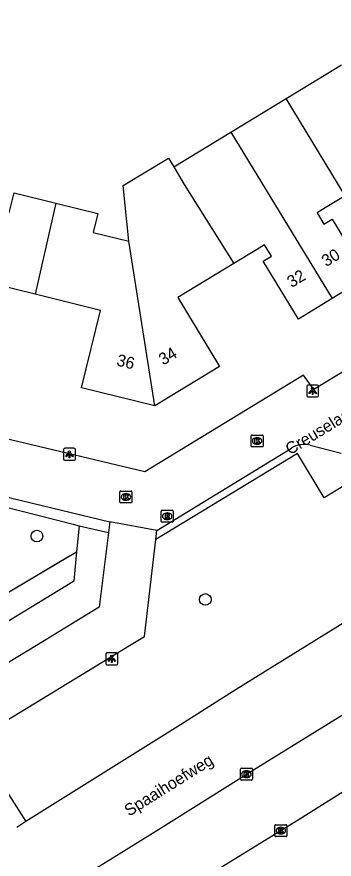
# Model space of a CAD drawing. Extents: x 157767 to 159171, y 387842 to 389425.
# Drawn here: x 158221.8 to 158248.5, y 388232 to 388302.9 of the extents above; entities that cross this region are included whole.
import ezdxf

# ---------------------------------------------------------------- set-up
doc = ezdxf.new("R2010")
doc.units = 0
for name, color, linetype in [('IMGEO_Boom', 7, 'Continuous'), ('IMGEO_Fietspad_gesloten', 7, 'Continuous'), ('IMGEO_Groenvoorziening', 7, 'Continuous'), ('IMGEO_Kolk', 7, 'Continuous'), ('IMGEO_Lichtpunt', 7, 'Continuous'), ('IMGEO_Muur', 7, 'Continuous'), ('IMGEO_Openbare_ruimte_label', 7, 'Continuous'), ('IMGEO_Pand', 7, 'Continuous'), ('IMGEO_Pand_nummerreeks', 7, 'Continuous'), ('IMGEO_Rijbaan_lokaal_gesloten', 7, 'Continuous'), ('IMGEO_Rijbaan_lokaal_open', 7, 'Continuous'), ('IMGEO_Rioolput', 7, 'Continuous'), ('IMGEO_Voetpad_open', 7, 'Continuous')]:
    doc.layers.add(name, color=color, linetype=linetype)

msp = doc.modelspace()

# ---------------------------------------------------------------- linework, layer by layer
at = {"layer": 'IMGEO_Boom'}
for centre in [(158223.515, 388259.204), (158237.678, 388253.874)]:
    msp.add_circle(centre, 0.489, dxfattribs=at)
at = {"layer": 'IMGEO_Fietspad_gesloten'}
for points in [[(158229.644, 388260.394), (158229.533, 388259.494)], [(158233.501, 388258.911), (158233.592, 388259.688)], [(158229.533, 388259.494), (158228.757, 388253.218), (158223.468, 388250), (158218.876, 388247.24), (158215.245, 388245.012)], [(158218.642, 388242.296), (158231.308, 388250), (158232.551, 388250.756), (158233.501, 388258.911)]]:
    msp.add_lwpolyline(points, dxfattribs=at)
at = {"layer": 'IMGEO_Groenvoorziening'}
msp.add_lwpolyline([(158198.647, 388271.084), (158207.528, 388256.281), (158219.17, 388253.347), (158226.854, 388257.889)], dxfattribs=at)
at = {"layer": 'IMGEO_Kolk'}
for p, q in [((158241.53, 388266.778), (158241.53, 388267.63)), ((158241.605, 388267.704), (158242.457, 388267.704)), ((158242.018, 388267.484), (158242.043, 388267.484)), ((158242.531, 388267.63), (158242.531, 388266.778)), ((158242.457, 388266.704), (158241.605, 388266.704)), ((158242.041, 388266.924), (158242.016, 388266.924)), ((158230.501, 388262.067), (158230.501, 388262.919)), ((158230.576, 388262.993), (158231.428, 388262.993)), ((158230.989, 388262.773), (158231.014, 388262.773)), ((158231.502, 388262.919), (158231.502, 388262.067)), ((158231.428, 388261.993), (158230.576, 388261.993)), ((158231.012, 388262.213), (158230.987, 388262.213)), ((158240.63, 388238.755), (158240.63, 388239.607)), ((158240.705, 388239.681), (158241.557, 388239.681)), ((158241.118, 388239.461), (158241.143, 388239.461)), ((158241.631, 388239.607), (158241.631, 388238.755)), ((158241.557, 388238.681), (158240.705, 388238.681)), ((158241.141, 388238.901), (158241.116, 388238.901)), ((158243.525, 388234.007), (158243.525, 388234.859)), ((158243.6, 388234.933), (158244.452, 388234.933)), ((158244.526, 388234.859), (158244.526, 388234.007)), ((158244.036, 388234.153), (158244.011, 388234.153)), ((158244.013, 388234.713), (158244.038, 388234.713)), ((158244.452, 388233.933), (158243.6, 388233.933))]:
    msp.add_line(p, q, dxfattribs=at)
for points in [[(158241.53, 388266.778), (158241.53, 388267.63)], [(158241.605, 388267.704), (158242.457, 388267.704)], [(158241.851, 388267.404), (158241.974, 388267.404), (158241.974, 388267.253), (158242.104, 388267.404), (158242.268, 388267.404), (158242.122, 388267.253), (158242.275, 388267.004), (158242.123, 388267.004), (158242.038, 388267.168), (158241.974, 388267.101), (158241.974, 388267.004), (158241.851, 388267.004), (158241.851, 388267.404)], [(158242.531, 388267.63), (158242.531, 388266.778)], [(158242.457, 388266.704), (158241.605, 388266.704)], [(158230.501, 388262.067), (158230.501, 388262.919)], [(158230.576, 388262.993), (158231.428, 388262.993)], [(158230.822, 388262.693), (158230.945, 388262.693), (158230.945, 388262.542), (158231.075, 388262.693), (158231.239, 388262.693), (158231.093, 388262.542), (158231.246, 388262.293), (158231.094, 388262.293), (158231.009, 388262.457), (158230.945, 388262.39), (158230.945, 388262.293), (158230.822, 388262.293), (158230.822, 388262.693)], [(158231.502, 388262.919), (158231.502, 388262.067)], [(158231.428, 388261.993), (158230.576, 388261.993)], [(158240.63, 388238.755), (158240.63, 388239.607)], [(158240.705, 388239.681), (158241.557, 388239.681)], [(158240.951, 388239.381), (158241.074, 388239.381), (158241.074, 388239.23), (158241.204, 388239.381), (158241.368, 388239.381), (158241.222, 388239.23), (158241.375, 388238.981), (158241.223, 388238.981), (158241.138, 388239.145), (158241.074, 388239.078), (158241.074, 388238.981), (158240.951, 388238.981), (158240.951, 388239.381)], [(158241.631, 388239.607), (158241.631, 388238.755)], [(158241.557, 388238.681), (158240.705, 388238.681)], [(158243.525, 388234.007), (158243.525, 388234.859)], [(158243.6, 388234.933), (158244.452, 388234.933)], [(158244.526, 388234.859), (158244.526, 388234.007)], [(158243.846, 388234.633), (158243.969, 388234.633), (158243.969, 388234.482), (158244.099, 388234.633), (158244.263, 388234.633), (158244.117, 388234.482), (158244.27, 388234.233), (158244.118, 388234.233), (158244.033, 388234.397), (158243.969, 388234.33), (158243.969, 388234.233), (158243.846, 388234.233), (158243.846, 388234.633)], [(158244.452, 388233.933), (158243.6, 388233.933)]]:
    msp.add_lwpolyline(points, dxfattribs=at)
for centre, start, end in [((158241.607, 388267.628), 91.55205, 178.44795), ((158241.607, 388267.628), 91.55205, 178.44795), ((158242.455, 388267.628), 1.55205, 88.44795), ((158242.455, 388267.628), 1.55205, 88.44795), ((158241.607, 388266.78), 181.55205, 268.44795), ((158241.607, 388266.78), 181.55205, 268.44795), ((158242.455, 388266.78), 271.55205, 358.44795), ((158242.455, 388266.78), 271.55205, 358.44795), ((158230.578, 388262.917), 91.55205, 178.44795), ((158230.578, 388262.917), 91.55205, 178.44795), ((158231.426, 388262.917), 1.55205, 88.44795), ((158231.426, 388262.917), 1.55205, 88.44795), ((158230.578, 388262.069), 181.55205, 268.44795), ((158230.578, 388262.069), 181.55205, 268.44795), ((158231.426, 388262.069), 271.55205, 358.44795), ((158231.426, 388262.069), 271.55205, 358.44795), ((158240.707, 388239.605), 91.55205, 178.44795), ((158240.707, 388239.605), 91.55205, 178.44795), ((158241.555, 388239.605), 1.55205, 88.44795), ((158241.555, 388239.605), 1.55205, 88.44795), ((158240.707, 388238.757), 181.55205, 268.44795), ((158240.707, 388238.757), 181.55205, 268.44795), ((158241.555, 388238.757), 271.55205, 358.44795), ((158241.555, 388238.757), 271.55205, 358.44795), ((158243.602, 388234.857), 91.55205, 178.44795), ((158243.602, 388234.857), 91.55205, 178.44795), ((158244.45, 388234.857), 1.55205, 88.44795), ((158244.45, 388234.857), 1.55205, 88.44795), ((158243.602, 388234.009), 181.55205, 268.44795), ((158243.602, 388234.009), 181.55205, 268.44795), ((158244.45, 388234.009), 271.55205, 358.44795), ((158244.45, 388234.009), 271.55205, 358.44795)]:
    msp.add_arc(centre, 0.0765, start, end, dxfattribs=at)
for centre, major_axis, ratio, start_param, end_param in [((158242.017, 388267.204), (-0.387, 0.002), 0.722429, 4.712389, 7.853982), ((158242.042, 388267.204), (-0.39, 0.002), 0.717154, 1.570796, 4.712389), ((158230.988, 388262.493), (-0.387, 0.002), 0.722429, 4.712389, 7.853982), ((158231.013, 388262.493), (-0.39, 0.002), 0.717154, 1.570796, 4.712389), ((158241.117, 388239.181), (-0.387, 0.002), 0.722429, 4.712389, 7.853982), ((158241.142, 388239.181), (-0.39, 0.002), 0.717154, 1.570796, 4.712389), ((158244.012, 388234.433), (-0.387, 0.002), 0.722429, 4.712389, 7.853982), ((158244.037, 388234.433), (-0.39, 0.002), 0.717154, 1.570796, 4.712389)]:
    msp.add_ellipse(centre, major_axis=major_axis, ratio=ratio, start_param=start_param, end_param=end_param, dxfattribs=at)
at = {"layer": 'IMGEO_Lichtpunt'}
for p, q in [((158246.203, 388271.808), (158246.203, 388271.001)), ((158246.203, 388271.808), (158246.203, 388271.001)), ((158247.105, 388271.903), (158246.297, 388271.903)), ((158247.105, 388271.903), (158246.297, 388271.903)), ((158247.199, 388271.001), (158247.199, 388271.808)), ((158247.199, 388271.001), (158247.199, 388271.808)), ((158246.297, 388270.907), (158247.105, 388270.907)), ((158246.297, 388270.907), (158247.105, 388270.907)), ((158225.752, 388266.489), (158225.752, 388265.682)), ((158225.752, 388266.489), (158225.752, 388265.682)), ((158226.654, 388266.584), (158225.846, 388266.584)), ((158226.654, 388266.584), (158225.846, 388266.584)), ((158226.748, 388265.682), (158226.748, 388266.489)), ((158226.748, 388265.682), (158226.748, 388266.489)), ((158225.846, 388265.588), (158226.654, 388265.588)), ((158225.846, 388265.588), (158226.654, 388265.588)), ((158229.313, 388249.288), (158229.313, 388248.481)), ((158229.313, 388249.288), (158229.313, 388248.481)), ((158230.215, 388249.383), (158229.407, 388249.383)), ((158230.215, 388249.383), (158229.407, 388249.383)), ((158230.309, 388248.481), (158230.309, 388249.288)), ((158230.309, 388248.481), (158230.309, 388249.288)), ((158229.407, 388248.387), (158230.215, 388248.387)), ((158229.407, 388248.387), (158230.215, 388248.387))]:
    msp.add_line(p, q, dxfattribs=at)
for points in [[(158246.577, 388271.472), (158246.616, 388271.444), (158246.428, 388271.182), (158246.39, 388271.209), (158246.577, 388271.472)], [(158246.679, 388271.424), (158246.726, 388271.424), (158246.726, 388271.102), (158246.679, 388271.102), (158246.679, 388271.424)], [(158246.789, 388271.444), (158246.827, 388271.471), (158247.014, 388271.209), (158246.975, 388271.181), (158246.789, 388271.444)], [(158226.126, 388266.153), (158226.165, 388266.125), (158225.977, 388265.863), (158225.939, 388265.89), (158226.126, 388266.153)], [(158226.228, 388266.105), (158226.275, 388266.105), (158226.275, 388265.783), (158226.228, 388265.783), (158226.228, 388266.105)], [(158226.338, 388266.125), (158226.376, 388266.152), (158226.563, 388265.89), (158226.524, 388265.862), (158226.338, 388266.125)], [(158229.687, 388248.952), (158229.726, 388248.924), (158229.538, 388248.662), (158229.5, 388248.689), (158229.687, 388248.952)], [(158229.899, 388248.924), (158229.937, 388248.951), (158230.124, 388248.689), (158230.085, 388248.661), (158229.899, 388248.924)], [(158229.789, 388248.904), (158229.836, 388248.904), (158229.836, 388248.582), (158229.789, 388248.582), (158229.789, 388248.904)]]:
    msp.add_lwpolyline(points, dxfattribs=at)
for centre in [(158246.702, 388271.606), (158226.251, 388266.287), (158229.812, 388249.086)]:
    msp.add_circle(centre, 0.0994, dxfattribs=at)
for centre, start, end in [((158246.297, 388271.808), 90, 180), ((158246.297, 388271.808), 90, 180), ((158247.105, 388271.808), 0, 90), ((158247.105, 388271.808), 0, 90), ((158246.297, 388271.001), 180, 270), ((158246.297, 388271.001), 180, 270), ((158247.105, 388271.001), 270, 0), ((158247.105, 388271.001), 270, 360), ((158225.846, 388266.489), 90, 180), ((158225.846, 388266.489), 90, 180), ((158226.654, 388266.489), 0, 90), ((158226.654, 388266.489), 0, 90), ((158225.846, 388265.682), 180, 270), ((158225.846, 388265.682), 180, 270), ((158226.654, 388265.682), 270, 0), ((158226.654, 388265.682), 270, 360), ((158229.407, 388249.288), 90, 180), ((158229.407, 388249.288), 90, 180), ((158230.215, 388249.288), 0, 90), ((158230.215, 388249.288), 0, 90), ((158229.407, 388248.481), 180, 270), ((158229.407, 388248.481), 180, 270), ((158230.215, 388248.481), 270, 0), ((158230.215, 388248.481), 270, 360)]:
    msp.add_arc(centre, 0.0946, start, end, dxfattribs=at)
at = {"layer": 'IMGEO_Muur'}
msp.add_lwpolyline([(158198.647, 388271.084), (158207.528, 388256.281), (158219.17, 388253.347), (158226.246, 388257.53)], dxfattribs=at)
at = {"layer": 'IMGEO_Pand'}
for points in [[(158244.472, 388296.002), (158249.114, 388298.821)], [(158239.829, 388293.184), (158244.472, 388296.002)], [(158249.439, 388287.82), (158244.472, 388296.002)], [(158235.014, 388290.26), (158239.829, 388293.184)], [(158239.829, 388293.184), (158248.334, 388279.175)], [(158231.253, 388283.998), (158230.769, 388288.676), (158234.575, 388290.987), (158235.014, 388290.26)], [(158235.014, 388290.26), (158235.908, 388288.78), (158240.073, 388282.124)], [(158218.323, 388287.105), (158221.183, 388286.399), (158221.593, 388288.059), (158225.118, 388287.189)], [(158249.439, 388287.82), (158247.754, 388286.797), (158247.071, 388286.382), (158247.651, 388285.428), (158248.333, 388285.842), (158251.292, 388280.971), (158248.334, 388279.175)], [(158225.118, 388287.189), (158223.365, 388279.536)], [(158225.118, 388287.189), (158228.636, 388286.32), (158228.246, 388284.74), (158231.253, 388283.998)], [(158233.425, 388270.159), (158231.253, 388283.998)], [(158248.334, 388279.175), (158245.499, 388277.454), (158242.54, 388282.327), (158243.225, 388282.743), (158242.65, 388283.689), (158241.966, 388283.273), (158240.073, 388282.124)], [(158240.073, 388282.124), (158235.352, 388279.257), (158238.87, 388273.463), (158233.425, 388270.159)], [(158223.365, 388279.536), (158217.865, 388280.894), (158216.219, 388274.228), (158209.965, 388275.772)], [(158233.425, 388270.159), (158227.258, 388271.682), (158228.863, 388278.178), (158223.365, 388279.536)]]:
    msp.add_lwpolyline(points, dxfattribs=at)
at = {"layer": 'IMGEO_Rijbaan_lokaal_gesloten'}
for points in [[(158293.929, 388279.825), (158284.109, 388273.656), (158271.906, 388265.997), (158262.426, 388260.118), (158253.604, 388254.566), (158246.245, 388250), (158242.941, 388247.95), (158240.03, 388246.171), (158235.601, 388243.333), (158222.599, 388235.192)], [(158225.956, 388229.686), (158228.439, 388231.238), (158233.827, 388234.591), (158241.948, 388239.696), (158252.21, 388246.033), (158253.486, 388246.832)], [(158256.361, 388242.184), (158254.243, 388240.849), (158245.553, 388235.376), (158238.633, 388231.098), (158230.073, 388225.616), (158228.915, 388224.902)], [(158222.599, 388235.192), (158221.83, 388234.711)]]:
    msp.add_lwpolyline(points, dxfattribs=at)
at = {"layer": 'IMGEO_Rijbaan_lokaal_open'}
for points in [[(158258.673, 388278.755), (158246.797, 388271.528), (158245.92, 388272.734), (158232.576, 388264.595), (158209.967, 388270.003)], [(158246.497, 388266.844), (158249.099, 388266.165)], [(158233.592, 388259.688), (158244.918, 388266.611)], [(158206.891, 388265.879), (158208.258, 388265.567), (158229.644, 388260.394)], [(158233.592, 388259.688), (158229.644, 388260.394)]]:
    msp.add_lwpolyline(points, dxfattribs=at)
msp.add_arc((158245.982, 388264.866), 2.044, 75.41529, 121.37289, dxfattribs=at)
at = {"layer": 'IMGEO_Rioolput'}
for p, q in [((158233.971, 388260.445), (158233.971, 388261.297)), ((158234.046, 388261.371), (158234.898, 388261.371)), ((158234.459, 388261.151), (158234.484, 388261.151)), ((158234.972, 388261.297), (158234.972, 388260.445)), ((158234.898, 388260.371), (158234.046, 388260.371)), ((158234.482, 388260.591), (158234.457, 388260.591))]:
    msp.add_line(p, q, dxfattribs=at)
for points in [[(158233.971, 388260.445), (158233.971, 388261.297)], [(158234.046, 388261.371), (158234.898, 388261.371)], [(158234.56, 388261.069), (158234.308, 388261.071), (158234.308, 388260.671)], [(158234.972, 388261.297), (158234.972, 388260.445)], [(158234.898, 388260.371), (158234.046, 388260.371)], [(158234.308, 388260.671), (158234.432, 388260.671), (158234.432, 388260.833), (158234.443, 388260.833)], [(158234.486, 388260.99), (158234.432, 388260.99), (158234.432, 388260.909)], [(158234.432, 388260.909), (158234.484, 388260.909)], [(158234.49, 388260.804), (158234.561, 388260.671), (158234.701, 388260.671), (158234.636, 388260.797)]]:
    msp.add_lwpolyline(points, dxfattribs=at)
for centre, radius, start, end in [((158234.048, 388261.295), 0.0765, 91.55205, 178.44795), ((158234.048, 388261.295), 0.0765, 91.55205, 178.44795), ((158234.559, 388260.959), 0.109, 350.36119, 89.41601), ((158234.896, 388261.295), 0.0765, 1.55205, 88.44795), ((158234.896, 388261.295), 0.0765, 1.55205, 88.44795), ((158234.048, 388260.447), 0.0765, 181.55205, 268.44795), ((158234.048, 388260.447), 0.0765, 181.55205, 268.44795), ((158234.442, 388260.78), 0.0533, 26.02933, 88.69889), ((158234.468, 388261.098), 0.19, 274.7715, 282.96867), ((158234.492, 388260.894), 0.0964, 77.00612, 93.18647), ((158234.506, 388260.951), 0.0378, 276.66336, 79.67722), ((158234.557, 388260.959), 0.112, 277.58423, 350.98172), ((158234.541, 388260.744), 0.108, 29.51342, 73.79051), ((158234.896, 388260.447), 0.0765, 271.55205, 358.44795), ((158234.896, 388260.447), 0.0765, 271.55205, 358.44795)]:
    msp.add_arc(centre, radius, start, end, dxfattribs=at)
for centre, major_axis, ratio, start_param, end_param in [((158234.458, 388260.871), (-0.387, 0.002), 0.722429, 4.712389, 7.853982), ((158234.483, 388260.871), (-0.39, 0.002), 0.717154, 1.570796, 4.712389)]:
    msp.add_ellipse(centre, major_axis=major_axis, ratio=ratio, start_param=start_param, end_param=end_param, dxfattribs=at)
at = {"layer": 'IMGEO_Voetpad_open'}
for points in [[(158186.634, 388310.76), (158183.422, 388300.898), (158183.553, 388299.72), (158204.079, 388265.917), (158226.561, 388260.197), (158227.06, 388260.07)], [(158292.328, 388282.456), (158283.833, 388284.506), (158247.662, 388262.433), (158245.424, 388266.158), (158233.501, 388258.911)], [(158227.06, 388260.07), (158226.854, 388257.889)], [(158227.06, 388260.07), (158229.533, 388259.494)], [(158226.854, 388257.889), (158226.619, 388255.406), (158225.948, 388254.997), (158217.748, 388250), (158210.686, 388245.697)], [(158218.481, 388241.599), (158222.599, 388235.192)]]:
    msp.add_lwpolyline(points, dxfattribs=at)

# ---------------------------------------------------------------- texts
at = {"layer": 'IMGEO_Openbare_ruimte_label'}
for s, rotation, p in [('Creuselaan', 31.38612, (158244.798, 388265.991)), ('Spaaihoefweg', 32.00538, (158231.262, 388235.598))]:
    msp.add_text(s, height=1, rotation=rotation, dxfattribs=at).set_placement(p)
at = {"layer": 'IMGEO_Pand_nummerreeks'}
for s, rotation, p in [('30', 31.26244, (158247.833, 388281.818)), ('32', 31.26244, (158244.931, 388280.056)), ('36', 346.11031, (158230.145, 388273.565)), ('34', 31.26631, (158234.133, 388273.535))]:
    msp.add_text(s, height=1, rotation=rotation, dxfattribs=at).set_placement(p)

doc.saveas('drawing.dxf')
